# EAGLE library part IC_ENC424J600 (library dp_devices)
Stand-Alone 10/100 Ethernet Controller with SPI or Parallel Interface Source: http://ww1.microchip.com/downloads/en/DeviceDoc/39935c.pdf
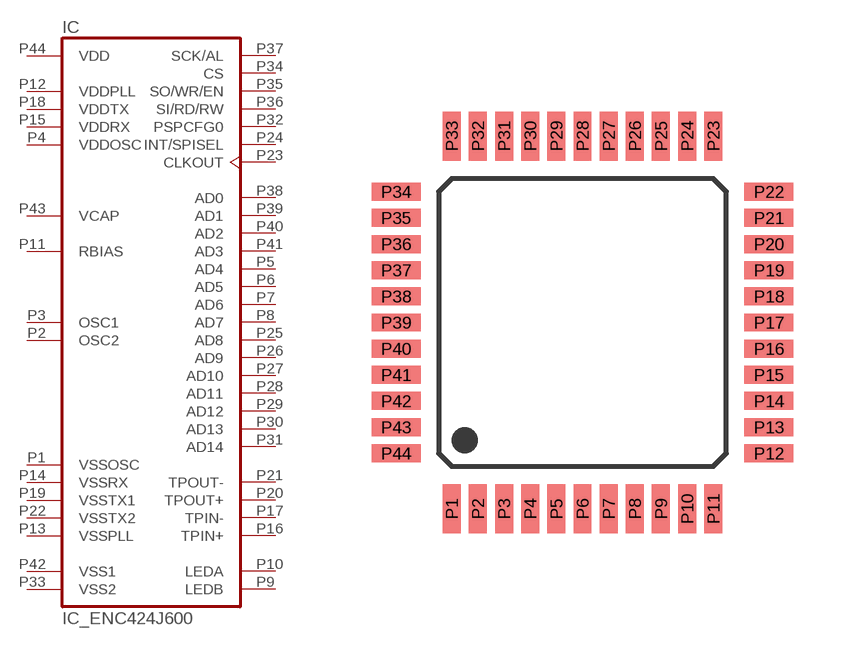
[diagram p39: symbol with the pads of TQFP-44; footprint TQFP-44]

Designator prefix IC

## IC_ENC424J600-TQFP44  [TQFP-44]
P1  VSSOSC  in
P2  OSC2  out
P3  OSC1  in
P4  VDDOSC  in
P5  AD4
P6  AD5
P7  AD6
P8  AD7
P9  LEDB  out
P10  LEDA  out
P11  RBIAS  in
P12  VDDPLL  in
P13  VSSPLL  in
P14  VSSRX  in
P15  VDDRX  in
P16  TPIN+  in
P17  TPIN-  in
P18  VDDTX  in
P19  VSSTX1  in
P20  TPOUT+  out
P21  TPOUT-  out
P22  VSSTX2  in
P23  CLKOUT  out
P24  INT/SPISEL
P25  AD8
P26  AD9
P27  AD10
P28  AD11
P29  AD12
P30  AD13
P31  AD14
P32  PSPCFG0  in
P33  VSS2  in
P34  CS  in
P35  SO/WR/EN
P36  SI/RD/RW  in
P37  SCK/AL  in
P38  AD0
P39  AD1  in
P40  AD2
P41  AD3
P42  VSS1  in
P43  VCAP  in
P44  VDD  in

## Footprint TQFP-44 (pad centres in mm)
smd 0.55 x 1.5: P1 -4,-5.7; P2 -3.2,-5.7; P3 -2.4,-5.7; P4 -1.6,-5.7; P5 -0.8,-5.7; P6 0,-5.7; P7 0.8,-5.7; P8 1.6,-5.7; P9 2.4,-5.7; P10 3.2,-5.7; P11 4,-5.7; P23 4,5.7; P24 3.2,5.7; P25 2.4,5.7; P26 1.6,5.7; P27 0.8,5.7; P28 0,5.7; P29 -0.8,5.7; P30 -1.6,5.7; P31 -2.4,5.7; P32 -3.2,5.7; P33 -4,5.7
smd 1.5 x 0.55: P12 5.7,-4; P13 5.7,-3.2; P14 5.7,-2.4; P15 5.7,-1.6; P16 5.7,-0.8; P17 5.7,0; P18 5.7,0.8; P19 5.7,1.6; P20 5.7,2.4; P21 5.7,3.2; P22 5.7,4; P34 -5.7,4; P35 -5.7,3.2; P36 -5.7,2.4; P37 -5.7,1.6; P38 -5.7,0.8; P39 -5.7,0; P40 -5.7,-0.8; P41 -5.7,-1.6; P42 -5.7,-2.4; P43 -5.7,-3.2; P44 -5.7,-4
